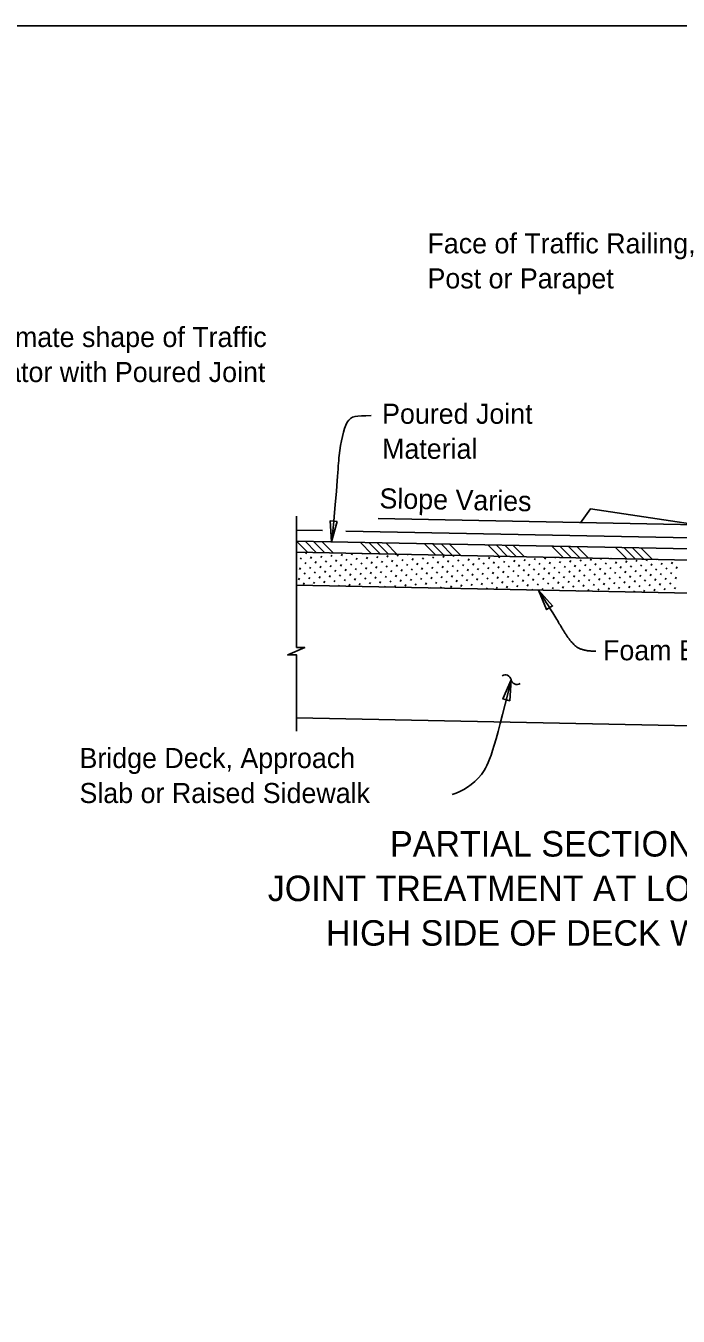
# Model space of a CAD drawing. Extents: x 0 to 15.4, y 0 to 9.7.
# Drawn here: x 10.216 to 12.677, y 4.865 to 9.73 of the extents above; entities that cross this region are included whole.
import ezdxf

# ---------------------------------------------------------------- set-up
doc = ezdxf.new("R2010")
doc.units = 0
for name, color, linetype in [('Dimension', 7, 'Continuous'), ('Miscellaneous', 7, 'Continuous'), ('Miscellaneous1', 7, 'Continuous'), ('SupstrConc', 7, 'Continuous'), ('TextStructures', 7, 'Continuous')]:
    doc.layers.add(name, color=color, linetype=linetype)

msp = doc.modelspace()

# ---------------------------------------------------------------- linework, layer by layer
at = {"layer": 'Dimension'}
for points in [[(11.2372, 7.0701), (11.2372, 7.3582), (11.2041, 7.3582), (11.2682, 7.3865), (11.2372, 7.3865), (11.2372, 7.8816)], [(12.3088, 7.8559), (12.3453, 7.9083), (12.7488, 7.8484), (11.5452, 7.8725)]]:
    msp.add_lwpolyline(points, dxfattribs=at)
for points in [[(11.3906, 7.8608), (11.3695, 7.7844), (11.3643, 7.8635)], [(12.1502, 7.6021), (12.1803, 7.5288), (12.2028, 7.5428)], [(12.0468, 7.2645), (12.0155, 7.1918), (12.0412, 7.1855)]]:
    msp.add_lwpolyline(points, close=True, dxfattribs=at)
for centre, start, end in [((12.0245, 7.2605), 10.958, 122.6852), ((12.0684, 7.269), 190.958, 302.6852)]:
    msp.add_arc(centre, 0.0224, start, end, dxfattribs=at)
for points, degree in [([(11.5183, 8.26), (11.4617, 8.26), (11.4248, 8.26), (11.393, 8.1095), (11.3928, 8.0119), (11.3695, 7.7844)], 3), ([(12.3657, 7.3719), (12.3078, 7.3719), (12.2611, 7.4199), (12.2278, 7.4777), (12.1503, 7.6021)], 2), ([(11.8246, 6.8315), (11.8618, 6.8434), (11.9476, 6.8965), (11.9806, 6.9925), (12.0467, 7.2646)], 3)]:
    msp.add_open_spline(points, degree=degree, dxfattribs=at)
at = {"layer": 'Miscellaneous'}
for p, q in [((11.2373, 7.7871), (11.2798, 7.7445)), ((11.2373, 7.7871), (13.3672, 7.7445)), ((11.2691, 7.7865), (11.3117, 7.7439)), ((11.3009, 7.7858), (11.3435, 7.7433)), ((11.3328, 7.7852), (11.3753, 7.7426)), ((13.3664, 7.7028), (11.2373, 7.7454)), ((11.2725, 7.7397), (11.2753, 7.7446)), ((11.3112, 7.743), (11.3117, 7.7439)), ((11.4062, 7.7317), (11.4095, 7.7373)), ((11.4449, 7.735), (11.4482, 7.7406)), ((11.4779, 7.7823), (11.5204, 7.7397)), ((11.4836, 7.7382), (11.4849, 7.7404)), ((11.5097, 7.7816), (11.5523, 7.7391)), ((11.5415, 7.781), (11.5841, 7.7384)), ((11.5734, 7.7804), (11.6159, 7.7378)), ((11.6173, 7.7302), (11.6205, 7.7358)), ((11.656, 7.7335), (11.658, 7.737)), ((11.7185, 7.7775), (11.761, 7.7349)), ((11.7503, 7.7768), (11.7929, 7.7343)), ((11.7821, 7.7762), (11.8247, 7.7336)), ((11.814, 7.7755), (11.8565, 7.733)), ((11.959, 7.7726), (12.0016, 7.7301)), ((11.9909, 7.772), (12.0334, 7.7294)), ((12.0227, 7.7714), (12.0653, 7.7288)), ((12.0546, 7.7707), (12.0971, 7.7282)), ((12.1996, 7.7678), (12.2422, 7.7253)), ((12.2315, 7.7672), (12.274, 7.7246)), ((12.2633, 7.7666), (12.3059, 7.724)), ((12.2951, 7.7659), (12.3377, 7.7234)), ((12.4402, 7.763), (12.4828, 7.7205)), ((12.4721, 7.7624), (12.5146, 7.7198)), ((12.5039, 7.7617), (12.5465, 7.7192)), ((12.5357, 7.7611), (12.5783, 7.7185)), ((11.2516, 7.7188), (11.2548, 7.7244)), ((11.2693, 7.7011), (11.2725, 7.7067)), ((11.287, 7.6834), (11.2902, 7.6889)), ((11.2902, 7.722), (11.2935, 7.7276)), ((11.3079, 7.7043), (11.3112, 7.7099)), ((11.3257, 7.6866), (11.3289, 7.6922)), ((11.3289, 7.7253), (11.3321, 7.7309)), ((11.3466, 7.7075), (11.3499, 7.7131)), ((11.3643, 7.6898), (11.3676, 7.6954)), ((11.3676, 7.7285), (11.3708, 7.7341)), ((11.3853, 7.7108), (11.3885, 7.7164)), ((11.403, 7.6931), (11.4062, 7.6987)), ((11.424, 7.714), (11.4272, 7.7196)), ((11.4417, 7.6963), (11.4449, 7.7019)), ((11.4626, 7.7173), (11.4659, 7.7229)), ((11.4803, 7.6996), (11.4836, 7.7052)), ((11.4981, 7.6818), (11.5013, 7.6874)), ((11.5013, 7.7205), (11.5045, 7.7261)), ((11.519, 7.7028), (11.5223, 7.7084)), ((11.5367, 7.6851), (11.54, 7.6907)), ((11.54, 7.7238), (11.5432, 7.7293)), ((11.5577, 7.706), (11.5609, 7.7116)), ((11.5754, 7.6883), (11.5786, 7.6939)), ((11.5786, 7.727), (11.5819, 7.7326)), ((11.5963, 7.7093), (11.5996, 7.7149)), ((11.6141, 7.6916), (11.6173, 7.6972)), ((11.635, 7.7125), (11.6383, 7.7181)), ((11.6527, 7.6948), (11.656, 7.7004)), ((11.6737, 7.7158), (11.6769, 7.7214)), ((11.6914, 7.698), (11.6946, 7.7036)), ((11.7124, 7.719), (11.7156, 7.7246)), ((11.7301, 7.7013), (11.7333, 7.7069)), ((11.7478, 7.6836), (11.751, 7.6892)), ((11.751, 7.7222), (11.7543, 7.7278)), ((11.7687, 7.7045), (11.772, 7.7101)), ((11.7865, 7.6868), (11.7897, 7.6924)), ((11.7897, 7.7255), (11.7929, 7.7311)), ((11.8074, 7.7078), (11.8107, 7.7134)), ((11.8251, 7.6901), (11.8284, 7.6957)), ((11.8284, 7.7287), (11.8311, 7.7335)), ((11.8461, 7.711), (11.8493, 7.7166)), ((11.8638, 7.6933), (11.867, 7.6989)), ((11.867, 7.732), (11.8675, 7.7328)), ((11.8848, 7.7142), (11.888, 7.7198)), ((11.9025, 7.6965), (11.9057, 7.7021)), ((11.9234, 7.7175), (11.9267, 7.7231)), ((11.9411, 7.6998), (11.9444, 7.7054)), ((11.9589, 7.6821), (11.9621, 7.6877)), ((11.9621, 7.7207), (11.9653, 7.7263)), ((11.9798, 7.703), (11.983, 7.7086)), ((11.9975, 7.6853), (12.0008, 7.6909)), ((12.0008, 7.724), (12.004, 7.7296)), ((12.0185, 7.7063), (12.0217, 7.7119)), ((12.0362, 7.6885), (12.0394, 7.6941)), ((12.0394, 7.7272), (12.0406, 7.7293)), ((12.0571, 7.7095), (12.0604, 7.7151)), ((12.0749, 7.6918), (12.0781, 7.6974)), ((12.0958, 7.7127), (12.0991, 7.7183)), ((12.1135, 7.695), (12.1168, 7.7006)), ((12.1345, 7.716), (12.1377, 7.7216)), ((12.1522, 7.6983), (12.1554, 7.7039)), ((12.1732, 7.7192), (12.1764, 7.7248)), ((12.1909, 7.7015), (12.1941, 7.7071)), ((12.2086, 7.6838), (12.2118, 7.6894)), ((12.2118, 7.7225), (12.2138, 7.7258)), ((12.2295, 7.7047), (12.2328, 7.7103)), ((12.2473, 7.687), (12.2505, 7.6926)), ((12.2682, 7.708), (12.2715, 7.7136)), ((12.2859, 7.6903), (12.2892, 7.6959)), ((12.3069, 7.7112), (12.3101, 7.7168)), ((12.3246, 7.6935), (12.3278, 7.6991)), ((12.3456, 7.7145), (12.3488, 7.7201)), ((12.3633, 7.6968), (12.3665, 7.7024)), ((12.3842, 7.7177), (12.3869, 7.7224)), ((12.4019, 7.7), (12.4052, 7.7056)), ((12.4197, 7.6823), (12.4229, 7.6879)), ((12.4229, 7.721), (12.4233, 7.7216)), ((12.4406, 7.7032), (12.4438, 7.7088)), ((12.4583, 7.6855), (12.4616, 7.6911)), ((12.4793, 7.7065), (12.4825, 7.7121)), ((12.497, 7.6888), (12.5002, 7.6944)), ((12.5179, 7.7097), (12.5212, 7.7153)), ((12.5357, 7.692), (12.5389, 7.6976)), ((12.5566, 7.713), (12.5599, 7.7186)), ((12.5743, 7.6952), (12.5776, 7.7008)), ((12.5953, 7.7162), (12.5964, 7.7182)), ((12.613, 7.6985), (12.6162, 7.7041)), ((12.6517, 7.7017), (12.6549, 7.7073)), ((12.6694, 7.684), (12.6726, 7.6896)), ((11.2451, 7.6414), (11.2483, 7.647)), ((11.2483, 7.6801), (11.2516, 7.6857)), ((11.266, 7.6624), (11.2693, 7.668)), ((11.2837, 7.6447), (11.287, 7.6503)), ((11.3047, 7.6656), (11.3079, 7.6712)), ((11.3224, 7.6479), (11.3257, 7.6535)), ((11.3434, 7.6689), (11.3466, 7.6745)), ((11.3611, 7.6512), (11.3643, 7.6568)), ((11.3788, 7.6334), (11.382, 7.639)), ((11.382, 7.6721), (11.3853, 7.6777)), ((11.3998, 7.6544), (11.403, 7.66)), ((11.4175, 7.6367), (11.4207, 7.6423)), ((11.4207, 7.6754), (11.424, 7.681)), ((11.4384, 7.6576), (11.4417, 7.6632)), ((11.4561, 7.6399), (11.4594, 7.6455)), ((11.4594, 7.6786), (11.4626, 7.6842)), ((11.4771, 7.6609), (11.4803, 7.6665)), ((11.4948, 7.6432), (11.4981, 7.6488)), ((11.5158, 7.6641), (11.519, 7.6697)), ((11.5335, 7.6464), (11.5367, 7.652)), ((11.5544, 7.6674), (11.5577, 7.673)), ((11.5722, 7.6497), (11.5754, 7.6553)), ((11.5931, 7.6706), (11.5963, 7.6762)), ((11.6108, 7.6529), (11.6141, 7.6585)), ((11.6285, 7.6352), (11.6318, 7.6408)), ((11.6318, 7.6738), (11.635, 7.6794)), ((11.6495, 7.6561), (11.6527, 7.6617)), ((11.6672, 7.6384), (11.6704, 7.644)), ((11.6704, 7.6771), (11.6737, 7.6827)), ((11.6882, 7.6594), (11.6914, 7.665)), ((11.7059, 7.6417), (11.7091, 7.6473)), ((11.7091, 7.6803), (11.7124, 7.6859)), ((11.7268, 7.6626), (11.7301, 7.6682)), ((11.7445, 7.6449), (11.7478, 7.6505)), ((11.7655, 7.6659), (11.7687, 7.6715)), ((11.7832, 7.6481), (11.7865, 7.6537)), ((11.8042, 7.6691), (11.8074, 7.6747)), ((11.8219, 7.6514), (11.8251, 7.657)), ((11.8396, 7.6337), (11.8428, 7.6393)), ((11.8428, 7.6723), (11.8461, 7.6779)), ((11.8606, 7.6546), (11.8638, 7.6602)), ((11.8783, 7.6369), (11.8815, 7.6425)), ((11.8815, 7.6756), (11.8848, 7.6812)), ((11.8992, 7.6579), (11.9025, 7.6635)), ((11.9169, 7.6402), (11.9202, 7.6457)), ((11.9202, 7.6788), (11.9234, 7.6844)), ((11.9379, 7.6611), (11.9411, 7.6667)), ((11.9556, 7.6434), (11.9589, 7.649)), ((11.9766, 7.6643), (11.9798, 7.6699)), ((11.9943, 7.6466), (11.9975, 7.6522)), ((12.0152, 7.6676), (12.0185, 7.6732)), ((12.033, 7.6499), (12.0362, 7.6555)), ((12.0539, 7.6708), (12.0571, 7.6764)), ((12.0716, 7.6531), (12.0749, 7.6587)), ((12.0893, 7.6354), (12.0926, 7.641)), ((12.0926, 7.6741), (12.0958, 7.6797)), ((12.1103, 7.6564), (12.1135, 7.662)), ((12.128, 7.6386), (12.1312, 7.6442)), ((12.1312, 7.6773), (12.1345, 7.6829)), ((12.149, 7.6596), (12.1522, 7.6652)), ((12.1667, 7.6419), (12.1699, 7.6475)), ((12.1699, 7.6806), (12.1732, 7.6861)), ((12.1876, 7.6628), (12.1909, 7.6684)), ((12.2053, 7.6451), (12.2086, 7.6507)), ((12.2263, 7.6661), (12.2295, 7.6717)), ((12.244, 7.6484), (12.2473, 7.654)), ((12.265, 7.6693), (12.2682, 7.6749)), ((12.2827, 7.6516), (12.2859, 7.6572)), ((12.3004, 7.6339), (12.3036, 7.6395)), ((12.3036, 7.6726), (12.3069, 7.6782)), ((12.3214, 7.6548), (12.3246, 7.6604)), ((12.3391, 7.6371), (12.3423, 7.6427)), ((12.3423, 7.6758), (12.3456, 7.6814)), ((12.36, 7.6581), (12.3633, 7.6637)), ((12.3777, 7.6404), (12.381, 7.646)), ((12.381, 7.679), (12.3842, 7.6846)), ((12.3987, 7.6613), (12.4019, 7.6669)), ((12.4164, 7.6436), (12.4197, 7.6492)), ((12.4374, 7.6646), (12.4406, 7.6702)), ((12.4551, 7.6469), (12.4583, 7.6525)), ((12.476, 7.6678), (12.4793, 7.6734)), ((12.4937, 7.6501), (12.497, 7.6557)), ((12.5115, 7.6324), (12.5147, 7.638)), ((12.5147, 7.671), (12.5179, 7.6766)), ((12.5324, 7.6533), (12.5357, 7.6589)), ((12.5501, 7.6356), (12.5534, 7.6412)), ((12.5534, 7.6743), (12.5566, 7.6799)), ((12.5711, 7.6566), (12.5743, 7.6622)), ((12.5888, 7.6389), (12.592, 7.6445)), ((12.592, 7.6775), (12.5953, 7.6831)), ((12.6098, 7.6598), (12.613, 7.6654)), ((12.6275, 7.6421), (12.6307, 7.6477)), ((12.6307, 7.6808), (12.634, 7.6864)), ((12.6484, 7.6631), (12.6517, 7.6687)), ((12.6661, 7.6453), (12.6694, 7.6509)), ((11.2373, 7.6204), (13.3849, 7.5774)), ((11.2628, 7.6237), (11.266, 7.6293)), ((11.3015, 7.627), (11.3047, 7.6326)), ((11.3401, 7.6302), (11.3434, 7.6358)), ((11.361, 7.6179), (11.3611, 7.6181)), ((11.3973, 7.6172), (11.3998, 7.6213)), ((11.4352, 7.619), (11.4384, 7.6246)), ((11.4739, 7.6222), (11.4771, 7.6278)), ((11.5125, 7.6255), (11.5158, 7.6311)), ((11.5512, 7.6287), (11.5544, 7.6343)), ((11.5705, 7.6137), (11.5722, 7.6166)), ((11.5899, 7.6319), (11.5931, 7.6375)), ((11.6076, 7.6142), (11.6108, 7.6198)), ((11.6463, 7.6175), (11.6495, 7.6231)), ((11.6849, 7.6207), (11.6882, 7.6263)), ((11.7236, 7.6239), (11.7268, 7.6295)), ((11.7436, 7.6102), (11.7445, 7.6118)), ((11.7623, 7.6272), (11.7655, 7.6328)), ((11.78, 7.6095), (11.7832, 7.6151)), ((11.8009, 7.6304), (11.8042, 7.636)), ((11.8186, 7.6127), (11.8219, 7.6183)), ((11.8573, 7.616), (11.8606, 7.6216)), ((11.896, 7.6192), (11.8992, 7.6248)), ((11.9168, 7.6068), (11.9169, 7.6071)), ((11.9347, 7.6224), (11.9379, 7.628)), ((11.9531, 7.606), (11.9556, 7.6103)), ((11.9733, 7.6257), (11.9766, 7.6313)), ((11.991, 7.608), (11.9943, 7.6136)), ((12.012, 7.6289), (12.0152, 7.6345)), ((12.0297, 7.6112), (12.033, 7.6168)), ((12.0507, 7.6322), (12.0539, 7.6378)), ((12.0684, 7.6144), (12.0716, 7.62)), ((12.107, 7.6177), (12.1103, 7.6233)), ((12.1263, 7.6026), (12.128, 7.6056)), ((12.1457, 7.6209), (12.149, 7.6265)), ((12.1634, 7.6032), (12.1667, 7.6088)), ((12.1844, 7.6242), (12.1876, 7.6298)), ((12.2021, 7.6065), (12.2053, 7.6121)), ((12.2231, 7.6274), (12.2263, 7.633)), ((12.2408, 7.6097), (12.244, 7.6153)), ((12.2617, 7.6306), (12.265, 7.6362)), ((12.2794, 7.6129), (12.2827, 7.6185)), ((12.2994, 7.5991), (12.3004, 7.6008)), ((12.3181, 7.6162), (12.3214, 7.6218)), ((12.3358, 7.5985), (12.3391, 7.6041)), ((12.3568, 7.6194), (12.36, 7.625)), ((12.3745, 7.6017), (12.3777, 7.6073)), ((12.3955, 7.6227), (12.3987, 7.6283)), ((12.4132, 7.6049), (12.4164, 7.6105)), ((12.4341, 7.6259), (12.4374, 7.6315)), ((12.4518, 7.6082), (12.4551, 7.6138)), ((12.4725, 7.5956), (12.4728, 7.5961)), ((12.4728, 7.6291), (12.476, 7.6347)), ((12.4905, 7.6114), (12.4937, 7.617)), ((12.5089, 7.5949), (12.5115, 7.5993)), ((12.5292, 7.6147), (12.5324, 7.6203)), ((12.5469, 7.597), (12.5501, 7.6025)), ((12.5678, 7.6179), (12.5711, 7.6235)), ((12.5856, 7.6002), (12.5888, 7.6058)), ((12.6065, 7.6211), (12.6098, 7.6267)), ((12.6242, 7.6034), (12.6275, 7.609)), ((12.6452, 7.6244), (12.6484, 7.63)), ((12.6629, 7.6067), (12.6661, 7.6123))]:
    msp.add_line(p, q, dxfattribs=at)
msp.add_lwpolyline([(0, 0), (15.394, 0), (15.394, 9.7298), (0, 9.7298)], close=True, dxfattribs=at)
at = {"layer": 'Miscellaneous1'}
msp.add_lwpolyline([(0, 9.7298), (15.394, 9.7298), (15.394, 0), (0, 0)], close=True, dxfattribs=at)
at = {"layer": 'SupstrConc'}
for p, q in [((11.2373, 7.8288), (11.3347, 7.8268)), ((11.423, 7.8251), (13.3049, 7.7874)), ((14.5576, 7.0541), (11.2372, 7.1205))]:
    msp.add_line(p, q, dxfattribs=at)

# ---------------------------------------------------------------- texts
at = {"layer": 'Dimension'}
for s, height, p in [('Face of Traffic Railing, ', 0.0756, (11.731, 8.8718)), ('Post or Parapet', 0.0756, (11.731, 8.7398)), ('Approximate shape of Traffic', 0.0756, (9.8323, 8.5187)), ('Separator with Poured Joint', 0.0756, (9.872, 8.3867)), ('Poured Joint ', 0.0756, (11.5599, 8.2294)), ('Material', 0.0756, (11.5599, 8.0974)), ('Bridge Deck, Approach ', 0.0756, (10.4185, 6.9315)), ('Slab or Raised Sidewalk', 0.0756, (10.4185, 6.7995)), ('PARTIAL SECTION ALONG ℄ JOINT', 0.096, (11.5898, 6.5978)), ('JOINT TREATMENT AT LOW SIDE OF DECK OR', 0.096, (11.1287, 6.4298)), ('HIGH SIDE OF DECK WITH SLOPES < 1%', 0.096, (11.3483, 6.2618))]:
    msp.add_text(s, height=height, dxfattribs=at).set_placement(p)
at = {"layer": 'TextStructures'}
msp.add_text('Slope Varies', height=0.0756, rotation=358.8543, dxfattribs=at).set_placement((11.5495, 7.9108))
msp.add_text('Foam Backer Rod', height=0.0756, dxfattribs=at).set_placement((12.3932, 7.3377))

doc.saveas('drawing.dxf')
